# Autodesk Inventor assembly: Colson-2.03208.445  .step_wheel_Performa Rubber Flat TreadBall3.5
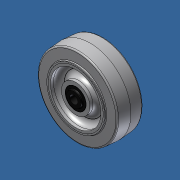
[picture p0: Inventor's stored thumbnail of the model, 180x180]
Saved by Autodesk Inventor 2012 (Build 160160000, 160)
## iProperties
Created: 2010-10
Part Number: Colson-2.03208.445  .step_wheel_Performa Rubber Flat TreadBall3.5
Document SubType Name: Assembly
Designer: Administrator
Mass: 248.42 g
Surface Area: 409.073 cm^2
Volume: 154.86 cm^3
Density: 1.60416 g/cm^3
Author: Administrator
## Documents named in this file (4)
- C:\Andys Backup Data\ANDY'S INVENTOR\INVENTOR LIBRARIES\PARTS LIBRARY\FEET WHEELS FLOOR FASTENING SUPPORTS\SUBCOMPONENTS\21.9403 wheel assy.iam
- C:\Andys Backup Data\ANDY'S INVENTOR\INVENTOR LIBRARIES\PARTS LIBRARY\FEET WHEELS FLOOR FASTENING SUPPORTS\SUBCOMPONENTS\21.9403 ball bearing.ipt
- C:\Andys Backup Data\ANDY'S INVENTOR\INVENTOR LIBRARIES\PARTS LIBRARY\FEET WHEELS FLOOR FASTENING SUPPORTS\SUBCOMPONENTS\21.9401 wheel tread.ipt
- C:\Andys Backup Data\ANDY'S INVENTOR\INVENTOR LIBRARIES\PARTS LIBRARY\FEET WHEELS FLOOR FASTENING SUPPORTS\SUBCOMPONENTS\21.9401 wheel core.ipt
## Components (3 placed, 3 different names)
1. 21.9403 ball bearing:1
2. 21.9401 wheel core:1
3. 21.9401 wheel tread:1
